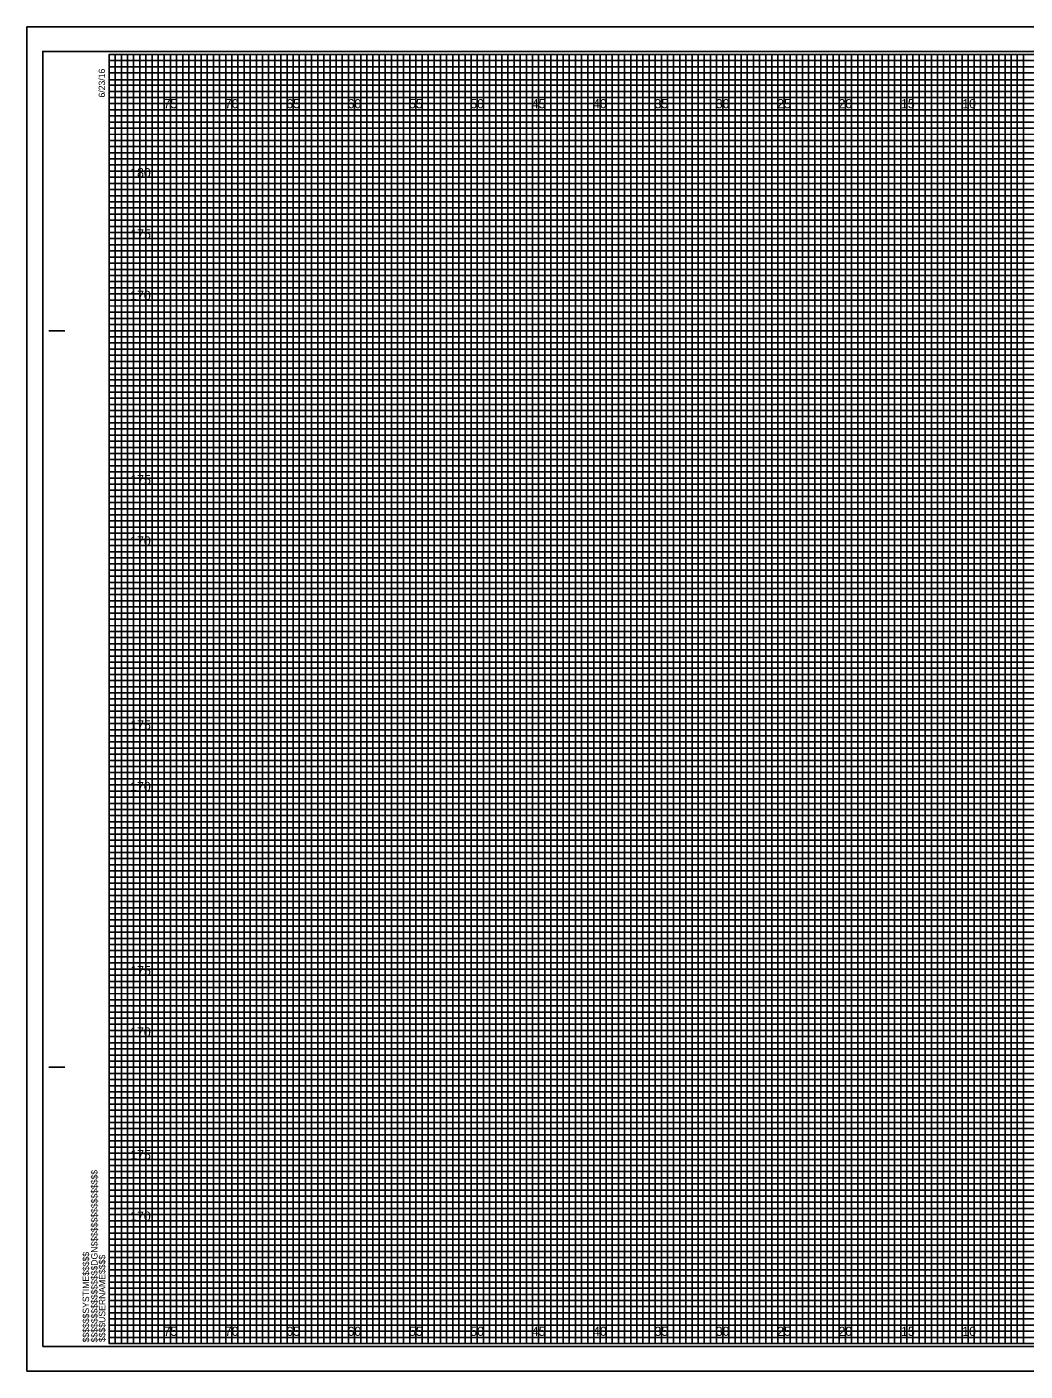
# Model space of a CAD drawing. Extents: x -7 to 162, y -2 to 107.
# Drawn here: x -6.7 to 74.6, y -2.3 to 107.3 of the extents above; entities that cross this region are included whole.
import ezdxf

# ---------------------------------------------------------------- set-up
doc = ezdxf.new("R2010")
doc.units = 0
for name, color, linetype in [('Prop CMT Conc Surface', 7, 'Continuous'), ('Prop CMT Pvmt Course 1', 7, 'Continuous'), ('Prop CMT Pvmt Wedge Surface 3', 7, 'Continuous'), ('Prop CMT Slope Grass', 7, 'Continuous'), ('Prop XS Earthwork Shape', 7, 'Continuous'), ('Prop XS Elevation Labels', 7, 'Continuous'), ('Prop XS SE Text', 7, 'Continuous'), ('Prop XS Side Slope Text', 7, 'Continuous'), ('Sheet Cutting Line CELL', 7, 'Continuous'), ('Sheet DOT Grid CELL', 7, 'Continuous'), ('Sheet Plot Border Inside CELL', 7, 'Continuous')]:
    doc.layers.add(name, color=color, linetype=linetype)

msp = doc.modelspace()

# ---------------------------------------------------------------- linework, layer by layer
at = {"layer": 'Prop CMT Conc Surface'}
for points in [[(0, 105), (2.5, 105), (2.5, 0), (7.5, 0), (7.5, 105), (12.5, 105), (12.5, 0), (17.5, 0), (17.5, 105), (22.5, 105), (22.5, 0), (27.5, 0), (27.5, 105), (32.5, 105), (32.5, 0), (37.5, 0), (37.5, 105), (42.5, 105), (42.5, 0), (47.5, 0), (47.5, 105), (52.5, 105), (52.5, 0), (57.5, 0), (57.5, 105), (62.5, 105), (62.5, 0), (67.5, 0), (67.5, 105), (72.5, 105), (72.5, 0), (77.5, 0)], [(0, 102.5), (137.5, 102.5)], [(0, 92.5), (160, 92.5), (160, 97.5), (0, 97.5)], [(0, 82.5), (160, 82.5), (160, 87.5), (0, 87.5)], [(0, 72.5), (160, 72.5), (160, 77.5), (0, 77.5)], [(0, 62.5), (160, 62.5), (160, 67.5), (0, 67.5)], [(0, 52.5), (160, 52.5), (160, 57.5), (0, 57.5)], [(0, 42.5), (160, 42.5), (160, 47.5), (0, 47.5)], [(0, 32.5), (160, 32.5), (160, 37.5), (0, 37.5)], [(0, 22.5), (160, 22.5), (160, 27.5), (0, 27.5)], [(0, 12.5), (160, 12.5), (160, 17.5), (0, 17.5)], [(0, 2.5), (160, 2.5), (160, 7.5), (0, 7.5)]]:
    msp.add_lwpolyline(points, dxfattribs=at)
at = {"layer": 'Prop CMT Pvmt Course 1'}
for p, q in [((5, 105), (0, 105)), ((5, 0), (5, 105)), ((15, 105), (10, 105)), ((10, 105), (10, 0)), ((15, 0), (15, 105)), ((25, 105), (20, 105)), ((20, 105), (20, 0)), ((25, 0), (25, 105)), ((35, 105), (30, 105)), ((30, 105), (30, 0)), ((35, 0), (35, 105)), ((45, 105), (40, 105)), ((40, 105), (40, 0)), ((45, 0), (45, 105)), ((55, 105), (50, 105)), ((50, 105), (50, 0)), ((55, 0), (55, 105)), ((65, 105), (60, 105)), ((60, 105), (60, 0)), ((65, 0), (65, 105)), ((75, 105), (70, 105)), ((70, 105), (70, 0)), ((10, 0), (5, 0)), ((20, 0), (15, 0)), ((30, 0), (25, 0)), ((40, 0), (35, 0)), ((50, 0), (45, 0)), ((60, 0), (55, 0)), ((70, 0), (65, 0))]:
    msp.add_line(p, q, dxfattribs=at)
for points in [[(0, 100), (160, 100), (160, 95), (0, 95)], [(0, 90), (160, 90), (160, 85), (0, 85)], [(0, 80), (160, 80), (160, 75), (0, 75)], [(0, 70), (160, 70), (160, 65), (0, 65)], [(0, 60), (160, 60), (160, 55), (0, 55)], [(0, 50), (160, 50), (160, 45), (0, 45)], [(0, 40), (160, 40), (160, 35), (0, 35)], [(0, 30), (160, 30), (160, 25), (0, 25)], [(0, 20), (160, 20), (160, 15), (0, 15)], [(0, 10), (160, 10), (160, 5), (0, 5)]]:
    msp.add_lwpolyline(points, dxfattribs=at)
at = {"layer": 'Prop CMT Slope Grass'}
for p, q in [((0, 104.5), (130, 104.5)), ((130, 103.99), (0, 103.99)), ((0, 103.99), (0, 103.5)), ((0, 103.5), (130, 103.5)), ((130, 102.95), (0, 102.95)), ((0, 102.95), (0, 102)), ((0, 102), (160, 102))]:
    msp.add_line(p, q, dxfattribs=at)
for points in [[(0, 101.5), (135, 101.5), (160, 101.5), (160, 101), (0, 101)], [(0, 100.5), (160, 100.5), (160, 99.5), (0, 99.5)], [(0, 99), (160, 99), (160, 98.5), (0, 98.49)], [(0, 98), (160, 98), (160, 97), (0, 97)], [(0, 96.5), (160, 96.5), (160, 96), (0, 96)], [(0, 95.5), (160, 95.5), (160, 94.5), (0, 94.5)], [(0, 94), (160, 94), (160, 93.5), (0, 93.5)], [(0, 93), (160, 93), (160, 92), (0, 92)], [(0, 91.5), (160, 91.5), (160, 91), (0, 91)], [(0, 90.5), (160, 90.5), (160, 89.5), (0, 89.5)], [(0, 89), (160, 89), (160, 88.5), (0, 88.5)], [(0, 88), (160, 88), (160, 86.98), (160, 86.5), (160, 86), (0, 86)], [(0, 87), (160, 87), (160, 86.5), (0, 86.5)], [(0, 85.5), (160, 85.5), (160, 84.5), (0, 84.52)], [(0, 84.52), (160, 84.5), (160, 84), (0, 84)], [(0, 83.5), (160, 83.5), (160, 83), (0, 83)], [(0, 82), (160, 82), (160, 81.5), (0, 81.5)], [(0, 81), (160, 81), (160, 80.5), (0, 80.5)], [(-0.04, 79.45), (160, 79.45), (160, 78.94), (-0.04, 78.94)], [(0, 78.5), (160, 78.5), (160, 78), (0, 78)], [(0, 77), (160, 77), (160, 76.5), (0, 76.5)], [(0, 76), (160, 76), (160, 75.5), (0, 75.5)], [(0, 74.5), (160, 74.5), (160, 74), (0, 74)], [(0, 73.5), (160, 73.5), (160, 73), (0, 73)], [(0, 72), (160, 72), (160, 71.5), (0, 71.5)], [(0, 71), (160, 71), (160, 70.5), (0, 70.5)], [(0, 69.5), (160, 69.5), (160, 68.99), (0, 69)], [(0, 68.5), (160, 68.5), (160, 68), (0, 68)], [(0, 67), (160, 67), (160, 66.5), (0, 66.5)], [(0, 66), (160, 66), (160, 65.5), (0, 65.5)], [(0, 64.5), (160, 64.5), (160, 64), (0, 64)], [(0, 63.5), (160, 63.5), (160, 63), (0, 63)], [(0, 62), (160, 62), (160, 61.5), (0, 61.5)], [(0, 61), (160, 61), (160, 60.5), (0, 60.5)], [(0, 59.5), (160, 59.5), (160, 59), (0, 59)], [(0, 58.5), (160.03, 58.45), (160, 58), (0, 58)], [(0, 57), (160, 57), (160, 56.5), (0, 56.5)], [(0, 56), (160, 56), (160, 55.5), (0, 55.5)], [(0, 54.5), (160, 54.5), (160, 54), (0, 54)], [(0, 53.5), (160, 53.5), (160, 53), (0, 53)], [(0, 52), (160, 52), (160, 51.5), (0, 51.5)], [(0, 51), (160, 51), (160, 50.5), (0, 50.5)], [(0, 49.5), (160, 49.5), (160, 49), (0, 49)], [(0, 48.5), (160, 48.5), (160, 48), (0, 48)], [(0, 47), (160, 47), (160, 46.5), (0, 46.5)], [(0, 46), (160, 46), (160, 45.5), (0, 45.5)], [(0, 44.5), (160, 44.5), (160, 44), (0, 44)], [(0, 43.5), (160, 43.5), (160, 43), (0, 43)], [(0, 42), (160, 42), (160, 41.5), (0, 41.5)], [(0, 41), (160, 41), (160, 40.5), (0, 40.5)], [(0, 39.5), (160, 39.5), (160, 38.99), (0, 39)], [(0, 38.5), (160, 38.5), (160, 38), (0, 38)], [(0, 37), (160, 37), (160, 36.5), (0, 36.5)], [(0, 36), (160, 36), (160, 35.5), (0, 35.5)], [(0, 34.5), (160, 34.5), (160, 34), (0, 34)], [(0, 33.5), (160, 33.5), (160, 33), (0, 33)], [(0, 32), (160, 32), (160, 31.5), (0, 31.5)], [(0, 31), (160, 31), (160, 30.5), (0, 30.5)], [(0, 29.5), (160, 29.5), (160, 29), (0, 29)], [(0, 28.5), (160.03, 28.46), (160, 28), (0, 28)], [(0, 27), (160, 27), (160, 26.5), (0, 26.5)], [(0, 26), (160, 26), (160, 25.5), (0, 25.5)], [(0, 24.5), (160, 24.5), (160, 24), (0, 24)], [(0, 23.5), (160, 23.5), (160, 23), (0, 23)], [(0, 22), (160, 22), (160, 21.5), (0, 21.5)], [(0, 21), (160, 21), (160, 20.5), (0, 20.5)], [(0, 19.5), (160, 19.5), (160, 19), (0, 19)], [(0, 18.5), (160, 18.5), (160, 18), (0, 18)], [(0, 17), (160, 17), (160, 16.5), (0, 16.5)], [(0, 16), (160, 16), (160, 15.5), (0, 15.5)], [(0, 14.5), (160, 14.5), (160, 14), (0, 14)], [(0, 13.5), (160, 13.5), (160, 13), (0, 13)], [(0, 12), (160, 12), (160, 11.5), (0, 11.5)], [(0, 11), (160, 11), (160, 10.5), (0, 10.5)], [(0, 9.5), (160, 9.5), (160, 9), (0, 9)], [(0, 8.5), (160, 8.5), (160, 8), (0, 8)], [(0, 7), (160, 7), (160, 6.5), (0, 6.5)], [(0, 6), (160, 6), (160, 5.5), (0, 5.5)], [(0, 4.5), (160, 4.5), (160, 4), (0, 4)], [(0, 3.5), (160, 3.5), (160, 3), (0, 3)], [(0, 2), (160, 2), (160, 1.5), (0, 1.5)], [(0, 1), (160, 1), (160, 0.5), (0, 0.5)]]:
    msp.add_lwpolyline(points, dxfattribs=at)
at = {"layer": 'Prop XS Earthwork Shape'}
msp.add_lwpolyline([(-6.7, -2.25), (161.65, -2.25), (161.65, 107.25), (-6.7, 107.25)], close=True, dxfattribs=at)
at = {"layer": 'Prop XS SE Text'}
for p, q in [((-4.9, 82.5), (-3.65, 82.5)), ((-4.85, 82.5), (-3.6, 82.5)), ((-4.9, 22.5), (-3.65, 22.5)), ((-4.85, 22.5), (-3.6, 22.5)), ((0, 0), (0, 0)), ((0, 0), (0, 0)), ((0, 0), (0, 0)), ((0, 0), (0, 0)), ((0, 0), (0, 0)), ((0, 0), (0, 0)), ((0, 0), (0, 0))]:
    msp.add_line(p, q, dxfattribs=at)
msp.add_lwpolyline([(160, 105), (0, 105), (0, 0), (160, 0)], close=True, dxfattribs=at)
at = {"layer": 'Prop XS Side Slope Text'}
for points in [[(0, 0), (0.5, 0), (0.5, 105), (1, 105), (1, 0)], [(1, 0), (1.5, 0), (1.5, 105), (2, 105), (2, 0)], [(2.5, 0), (3, 0), (3, 105), (3.5, 105), (3.5, 0)], [(3.5, 0), (4, 0), (4, 105), (4.5, 105), (4.5, 0)], [(5, 0), (5.5, 0), (5.5, 105), (6, 105), (6, 0)], [(6, 0), (6.5, 0), (6.5, 105), (7, 105), (7, 0)], [(7.5, 0), (8, 0), (8, 105), (8.5, 105), (8.5, 0)], [(8.5, 0), (9, 0), (9, 105), (9.5, 105), (9.5, 0)], [(10, 0), (10.5, 0), (10.5, 105), (11, 105), (11, 0)], [(11, 0), (11.5, 0), (11.5, 105), (12, 105), (12, 0)], [(12.5, 0), (13, 0), (13, 105), (13.5, 105), (13.5, 0)], [(13.5, 0), (14, 0), (14, 105), (14.5, 105), (14.5, 0)], [(15, 0), (15.5, 0), (15.5, 105), (16, 105), (16, 0)], [(16, 0), (16.5, 0), (16.5, 105), (17, 105), (17, 0)], [(17.5, 0), (18, 0), (18, 105), (18.5, 105), (18.5, 0)], [(18.5, 0), (19, 0), (19, 105), (19.5, 105), (19.5, 0)], [(20, 0), (20.5, 0), (20.5, 105), (21, 105), (21, 0)], [(21, 0), (21.5, 0), (21.5, 105), (22, 105), (22, 0)], [(22.5, 0), (23, 0), (23, 105), (23.5, 105), (23.5, 0)], [(23.5, 0), (24, 0), (24, 105), (24.5, 105), (24.5, 0)], [(25, 0), (25.5, 0), (25.5, 105), (26, 105), (26, 0)], [(26, 0), (26.5, 0), (26.5, 105), (27, 105), (27, 0)], [(27.5, 0), (28, 0), (28, 105), (28.5, 105), (28.5, 0)], [(28.5, 0), (29, 0), (29, 105), (29.5, 105), (29.5, 0)], [(30, 0), (30.5, 0), (30.5, 105), (31, 105), (31, 0)], [(31, 0), (31.5, 0), (31.5, 105), (32, 105), (32, 0)], [(32.5, 0), (33, 0), (33, 105), (33.5, 105), (33.5, 0)], [(33.5, 0), (34, 0), (34, 105), (34.5, 105), (34.5, 0)], [(35, 0), (35.5, 0), (35.5, 105), (36, 105), (36, 0)], [(36, 0), (36.5, 0), (36.5, 105), (37, 105), (37, 0)], [(37.5, 0), (38, 0), (38, 105), (38.5, 105), (38.5, 0)], [(38.5, 0), (39, 0), (39, 105), (39.5, 105), (39.5, 0)], [(40, 0), (40.5, 0), (40.5, 105), (41, 105), (41, 0)], [(41, 0), (41.5, 0), (41.5, 105), (42, 105), (42, 0)], [(42.5, 0), (43, 0), (43, 105), (43.5, 105), (43.5, 0)], [(43.5, 0), (44, 0), (44, 105), (44.5, 105), (44.5, 0)], [(45, 0), (45.5, 0), (45.5, 105), (46, 105), (46, 0)], [(46, 0), (46.5, 0), (46.5, 105), (47, 105), (47, 0)], [(47.5, 0), (48, 0), (48, 105), (48.5, 105), (48.5, 0)], [(48.5, 0), (49, 0), (49, 105), (49.5, 105), (49.5, 0)], [(50, 0), (50.5, 0), (50.5, 105), (51, 105), (51, 0)], [(51, 0), (51.5, 0), (51.5, 105), (52, 105), (52, 0)], [(52.5, 0), (53, 0), (53, 105), (53.5, 105), (53.5, 0)], [(53.5, 0), (54, 0), (54, 105), (54.5, 105), (54.5, 0)], [(55, 0), (55.5, 0), (55.5, 105), (56, 105), (56, 0)], [(56, 0), (56.5, 0), (56.5, 105), (57, 105), (57, 0)], [(57.5, 0), (58, 0), (58, 105), (58.5, 105), (58.5, 0)], [(58.5, 0), (59, 0), (59, 105), (59.5, 105), (59.5, 0)], [(60, 0), (60.5, 0), (60.5, 105), (61, 105), (61, 0)], [(61, 0), (61.5, 0), (61.5, 105), (62, 105), (62, 0)], [(62.5, 0), (63, 0), (63, 105), (63.5, 105), (63.5, 0)], [(63.5, 0), (64, 0), (64, 105), (64.5, 105), (64.5, 0)], [(65, 0), (65.5, 0), (65.5, 105), (66, 105), (66, 0)], [(66, 0), (66.5, 0), (66.5, 105), (67, 105), (67, 0)], [(67.5, 0), (68, 0), (68, 105), (68.5, 105), (68.5, 0)], [(68.5, 0), (69, 0), (69, 105), (69.5, 105), (69.5, 0)], [(70, 0), (70.5, 0), (70.5, 105), (71, 105), (71, 0)], [(71, 0), (71.5, 0), (71.5, 105), (72, 105), (72, 0)], [(72.5, 0), (73, 0), (73, 105), (73.5, 105), (73.5, 0)], [(73.5, 0), (74, 0), (74, 105), (74.5, 105), (74.5, 0)]]:
    msp.add_lwpolyline(points, dxfattribs=at)
at = {"layer": 'Sheet Cutting Line CELL'}
for p, q in [((161.65, 107.25), (-6.7, 107.25)), ((-6.7, 107.25), (-6.7, -2.25)), ((-6.7, -2.25), (161.65, -2.25))]:
    msp.add_line(p, q, dxfattribs=at)
at = {"layer": 'Sheet DOT Grid CELL'}
for p, q in [((5, 0), (5, 105)), ((10, 0), (10, 105)), ((15, 0), (15, 105)), ((20, 0), (20, 105)), ((25, 0), (25, 105)), ((30, 0), (30, 105)), ((35, 0), (35, 105)), ((40, 0), (40, 105)), ((45, 0), (45, 105)), ((50, 0), (50, 105)), ((55, 0), (55, 105)), ((60, 0), (60, 105)), ((65, 0), (65, 105)), ((70, 0), (70, 105)), ((0, 100), (160, 100)), ((0, 95), (160, 95)), ((0, 90), (160, 90)), ((0, 85), (160, 85)), ((0, 80), (160, 80)), ((0, 75), (160, 75)), ((0, 70), (160, 70)), ((0, 65), (160, 65)), ((0, 60), (160, 60)), ((0, 55), (160, 55)), ((0, 50), (160, 50)), ((0, 45), (160, 45)), ((0, 40), (160, 40)), ((0, 35), (160, 35)), ((0, 30), (160, 30)), ((0, 25), (160, 25)), ((0, 20), (160, 20)), ((0, 15), (160, 15)), ((0, 10), (160, 10)), ((0, 5), (160, 5))]:
    msp.add_line(p, q, dxfattribs=at)
at = {"layer": 'Sheet Plot Border Inside CELL'}
msp.add_lwpolyline([(-5.4, -0.25), (161.2, -0.25), (161.2, 105.25), (-5.4, 105.25)], close=True, dxfattribs=at)

# ---------------------------------------------------------------- texts
at = {"layer": 'Prop CMT Pvmt Wedge Surface 3'}
for s, p in [('75', (4.44, 100.62)), ('70', (9.43, 100.62)), ('65', (14.44, 100.62)), ('60', (19.43, 100.62)), ('55', (24.44, 100.62)), ('50', (29.43, 100.62)), ('45', (34.44, 100.62)), ('40', (39.43, 100.62)), ('35', (44.44, 100.62)), ('30', (49.43, 100.62)), ('25', (54.44, 100.62)), ('20', (59.43, 100.62)), ('15', (64.53, 100.62)), ('10', (69.52, 100.62)), ('75', (4.44, 0.62)), ('70', (9.43, 0.62)), ('65', (14.44, 0.62)), ('60', (19.43, 0.62)), ('55', (24.44, 0.62)), ('50', (29.43, 0.62)), ('45', (34.44, 0.62)), ('40', (39.43, 0.62)), ('35', (44.44, 0.62)), ('30', (49.43, 0.62)), ('25', (54.44, 0.62)), ('20', (59.43, 0.62)), ('15', (64.53, 0.62)), ('10', (69.52, 0.62))]:
    msp.add_text(s, height=0.75, dxfattribs=at).set_placement(p)
at = {"layer": 'Prop XS Elevation Labels'}
for s, p in [('180', (1.72, 95)), ('175', (1.73, 90)), ('170', (1.72, 85)), ('175', (1.73, 70)), ('170', (1.72, 65)), ('175', (1.73, 50)), ('170', (1.72, 45)), ('175', (1.73, 30)), ('170', (1.72, 25)), ('175', (1.73, 15)), ('170', (1.72, 10))]:
    msp.add_text(s, height=0.75, dxfattribs=at).set_placement(p)
at = {"layer": 'Prop XS SE Text'}
for s, p in [('6/23/16', (-0.33, 101.5)), ('$$$$$$$$$$$$$$$$DGN$$$$$$$$$$$$$$$$', (-0.94, 0.09)), ('$$$$$$SYSTIME$$$$$', (-1.63, 0.09)), ('$$$$USERNAME$$$$', (-0.31, 0.12))]:
    msp.add_text(s, height=0.525, rotation=90, dxfattribs=at).set_placement(p)

doc.saveas('drawing.dxf')
